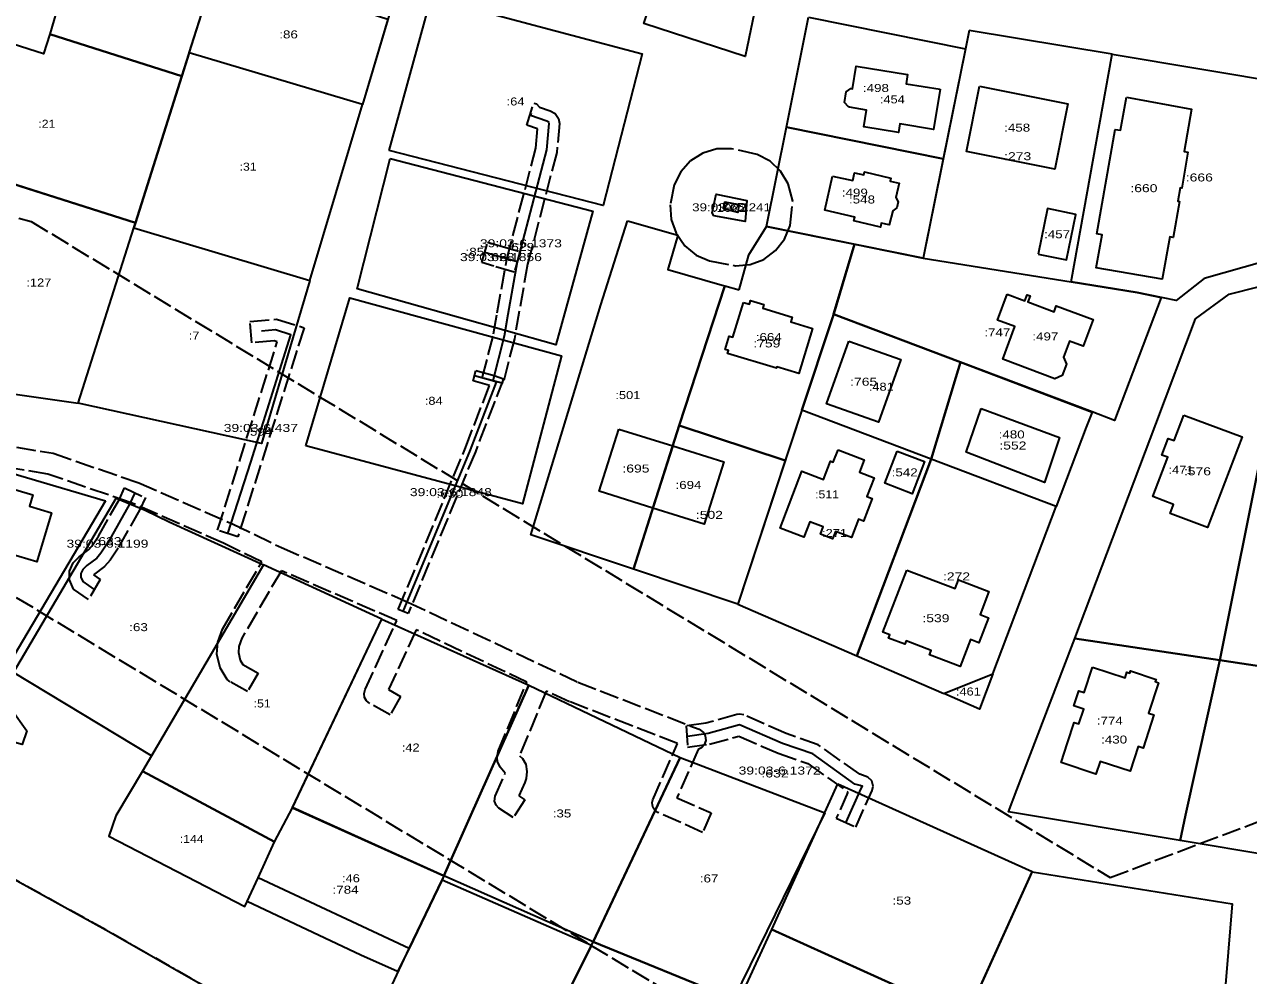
# Model space of a CAD drawing. Extents: x 1185507 to 1197690, y 352608 to 375774.
# Drawn here: x 1190677.6 to 1190907.1, y 364315.6 to 364493.9 of the extents above; entities that cross this region are included whole.
import ezdxf
from ezdxf.enums import TextEntityAlignment as Align

# ---------------------------------------------------------------- set-up
doc = ezdxf.new("R2010")
doc.units = 0
doc.header["$LTSCALE"] = 0.6
doc.linetypes.add('DOT_DASHED', pattern=[7.7, 5, -1.2, 0.3, -1.2])
doc.linetypes.add('LONG_DASHED', pattern=[7.5, 6, -1.5])
for name, color, linetype, lineweight in [('2', 7, 'Continuous', 35), ('4', 7, 'Continuous', 35), ('5', 7, 'DOT_DASHED', 35), ('7', 7, 'LONG_DASHED', 35), ('8', 7, 'Continuous', 35)]:
    doc.layers.add(name, color=color, linetype=linetype, lineweight=lineweight)

msp = doc.modelspace()

# ---------------------------------------------------------------- linework, layer by layer
at = {"layer": '2'}
for points in [[(1190719.02, 364521.51), (1190687.19, 364531.61), (1190680.16, 364509.45), (1190686.26, 364505.38), (1190682.39, 364492.06), (1190707.18, 364484.19)], [(1190719.02, 364521.51), (1190750.74, 364511.45), (1190741, 364478.87), (1190708.55, 364488.55)], [(1190713.83, 364505.16), (1190745.78, 364494.86), (1190741, 364478.87), (1190708.55, 364488.55)], [(1190794.51, 364502.32), (1190815.14, 364499.34), (1190812.76, 364487.9), (1190793.8, 364494.04), (1190796.36, 364501.72)], [(1190746, 364470.23), (1190753.87, 364498.94), (1190793.44, 364488.37), (1190786.14, 364459.95)], [(1190824.65, 364495.22), (1190854.06, 364489.3), (1190849.91, 364468.72), (1190820.51, 364474.64)], [(1190682.39, 364492.06), (1190681.23, 364488.39), (1190664.07, 364493.84), (1190656.51, 364470), (1190698.44, 364456.69), (1190707.18, 364484.19)], [(1190854.77, 364492.73), (1190854.06, 364489.3), (1190846.16, 364450.09), (1190873.92, 364445.64), (1190881.57, 364488.28)], [(1190708.55, 364488.55), (1190707.18, 364484.19), (1190698.44, 364456.69), (1190698.15, 364455.75), (1190731.18, 364445.9), (1190741, 364478.87)], [(1190881.57, 364488.28), (1190914.8, 364482.77), (1190921.92, 364481.47), (1190915.94, 364453.04), (1190913.8, 364450.48), (1190898.8, 364446.24), (1190893.57, 364442.12), (1190886.29, 364443.64), (1190873.92, 364445.64)], [(1190820.51, 364474.64), (1190849.91, 364468.72), (1190846.16, 364450.09), (1190816.75, 364456.02)], [(1190698.44, 364456.69), (1190662.46, 364468.12), (1190662.24, 364426.49), (1190687.72, 364422.9), (1190698.15, 364455.75)], [(1190746.24, 364468.74), (1190784.19, 364458.88), (1190777.27, 364433.8), (1190740, 364444.35)], [(1190806.88, 364458.01), (1190806.59, 364458.54), (1190807.34, 364462.04), (1190813.08, 364460.87), (1190812.79, 364456.95)], [(1190790.71, 364457.07), (1190800.12, 364454.38), (1190798.27, 364447.95), (1190808.46, 364445.03), (1190808.95, 364444.89), (1190800.4, 364418.7), (1190791.84, 364391.75), (1190772.61, 364398.19), (1190785.72, 364441.31)], [(1190698.15, 364455.75), (1190731.18, 364445.9), (1190722.07, 364415.36), (1190687.72, 364422.9)], [(1190811.63, 364444.12), (1190813.48, 364450.72), (1190816.75, 364456.02), (1190833.27, 364452.69), (1190829.37, 364439.63), (1190829.21, 364439.1), (1190823.42, 364421.57), (1190820.3, 364412.16), (1190800.4, 364418.7), (1190808.95, 364444.89)], [(1190833.27, 364452.69), (1190846.16, 364450.09), (1190873.92, 364445.64), (1190886.29, 364443.64), (1190890.75, 364442.71), (1190882.01, 364419.64), (1190877.8, 364421.24), (1190853.16, 364430.57), (1190829.36, 364439.59)], [(1190914.39, 364446.09), (1190909.87, 364415.25), (1190901.75, 364374.72), (1190874.57, 364378.76), (1190889.75, 364418.95), (1190897.19, 364438.67), (1190903.51, 364443.35)], [(1190914.39, 364446.09), (1190917.9, 364438.19), (1190925.84, 364435.48), (1190928.4, 364432.38), (1190929.16, 364411.7), (1190930.24, 364382.97), (1190930.46, 364376.9), (1190930.71, 364370.41), (1190917.36, 364372.4), (1190911.27, 364373.3), (1190901.75, 364374.72), (1190909.87, 364415.25)], [(1190730.4, 364414.92), (1190738.68, 364442.62), (1190778.35, 364431.75), (1190771.01, 364404.05)], [(1190829.21, 364439.1), (1190829.36, 364439.59), (1190853.16, 364430.57), (1190852.29, 364427.69), (1190847.67, 364412.37), (1190823.42, 364421.57)], [(1190852.29, 364427.69), (1190853.16, 364430.57), (1190877.8, 364421.23), (1190876.73, 364418.41), (1190871.08, 364403.5), (1190847.67, 364412.37)], [(1190823.42, 364421.57), (1190811.39, 364385.21), (1190833.72, 364375.54), (1190847.67, 364412.37)], [(1190800.4, 364418.7), (1190820.3, 364412.16), (1190811.39, 364385.21), (1190791.84, 364391.75)], [(1190692.85, 364404.6), (1190672.17, 364369.74), (1190678.11, 364361.49), (1190677.19, 364358.9), (1190651.89, 364365.81), (1190654.11, 364375.27), (1190663.17, 364413.36)], [(1190847.67, 364412.37), (1190833.72, 364375.54), (1190850.03, 364368.47), (1190859.2, 364372.14), (1190871.08, 364403.5)], [(1190694.85, 364405.06), (1190700.3, 364402.84), (1190704.79, 364400.65), (1190722.45, 364392.56), (1190701.47, 364356.76), (1190675.62, 364372.41)], [(1190722.45, 364392.56), (1190699.8, 364353.89), (1190724.53, 364340.65), (1190727.9, 364347.03), (1190744.63, 364382.42)], [(1190744.63, 364382.42), (1190772.2, 364370.06), (1190761.1, 364345.11), (1190756.27, 364334.27), (1190727.93, 364347.09)], [(1190874.57, 364378.76), (1190901.75, 364374.72), (1190895.36, 364345.65), (1190894.32, 364340.92), (1190862.14, 364346.31), (1190863.68, 364350.39), (1190873.96, 364377.16)], [(1190901.75, 364374.72), (1190911.27, 364373.3), (1190917.36, 364372.4), (1190930.71, 364370.41), (1190931.6, 364338.75), (1190914.65, 364338.2), (1190911.54, 364338.02), (1190894.32, 364340.92), (1190895.36, 364345.65)], [(1190850.03, 364368.47), (1190859.2, 364372.14), (1190856.72, 364365.55)], [(1190772.18, 364370.04), (1190800.59, 364356.46), (1190784.3, 364321.94), (1190756.27, 364334.27), (1190761.1, 364345.11)], [(1190800.59, 364356.46), (1190827.72, 364346.08), (1190810.56, 364311.15), (1190784.3, 364321.94)], [(1190724.53, 364340.65), (1190699.8, 364353.89), (1190694.75, 364345.53), (1190693.48, 364341.71), (1190718.98, 364328.52), (1190721.45, 364333.92)], [(1190830.12, 364351.57), (1190866.56, 364335.08), (1190854.19, 364307.74), (1190817.75, 364324.23)], [(1190727.9, 364347.03), (1190756.27, 364334.27), (1190755.93, 364333.55), (1190749.79, 364320.65), (1190747.6, 364316.36), (1190740.71, 364319.42), (1190719.43, 364329.5), (1190721.45, 364333.92), (1190724.53, 364340.65)], [(1190727.9, 364347.03), (1190756.27, 364334.27), (1190749.79, 364320.65), (1190721.45, 364333.92), (1190724.53, 364340.65)], [(1190866.56, 364335.07), (1190904.08, 364329.02), (1190899.68, 364276.2), (1190843.91, 364285.02), (1190854.19, 364307.74)], [(1190755.93, 364333.55), (1190783.97, 364321.28), (1190779.44, 364312.21), (1190772.48, 364297.77), (1190767.95, 364289.05), (1190741.88, 364303.85), (1190749.79, 364320.65)], [(1190841.33, 364280.15), (1190834.58, 364277.69), (1190809.79, 364289.26), (1190803.07, 364292.4), (1190811.54, 364310.75), (1190813.01, 364313.94), (1190817.75, 364324.23), (1190854.19, 364307.74), (1190843.91, 364285.02)], [(1190784.3, 364321.94), (1190810.56, 364311.15), (1190811.54, 364310.75), (1190803.07, 364292.4), (1190772.48, 364297.77), (1190779.44, 364312.21)]]:
    msp.add_lwpolyline(points, close=True, dxfattribs=at)
at = {"layer": '4'}
msp.add_lwpolyline([(1190647.14, 364349.43), (1190692.88, 364324.17), (1190757.05, 364287.63), (1190847.4, 364236.46), (1190870.47, 364225.86), (1190887.93, 364229.43), (1190903.2, 364233), (1190963.17, 364257.43), (1190977.58, 364249.06), (1191018.45, 364240.46), (1191053.56, 364275.17), (1191077.75, 364294.16)], dxfattribs=at)
at = {"layer": '5'}
msp.add_lwpolyline([(1190977.58, 364249.06), (1190963.17, 364257.43), (1190903.2, 364233), (1190887.93, 364229.43), (1190870.47, 364225.86), (1190847.4, 364236.46), (1190757.05, 364287.63), (1190692.88, 364324.17), (1190647.14, 364349.43), (1190632.21, 364356.82), (1190626.4, 364363.08), (1190622.19, 364369.01), (1190611.28, 364369.51), (1190595.22, 364367.23), (1190532.29, 364357.36), (1190463.09, 364355.18), (1190404.66, 364360.8), (1190352.99, 364368.35)], dxfattribs=at)
at = {"layer": '7'}
for points in [[(1189191.9, 364549.27), (1189395.22, 364588.56), (1189548.85, 364595.13), (1189680.04, 364579.91), (1189784.57, 364598.37), (1189872.95, 364591.01), (1190232.66, 364472.66), (1190283.77, 364463.98), (1190368.24, 364469.75), (1190452.8, 364459.37), (1190615.51, 364473.08), (1190678.91, 364456.96), (1190881.18, 364333.99), (1190940.56, 364356.34), (1190991.35, 364354.82), (1191177.32, 364502.05)], [(1189181.53, 364482.48), (1189344.66, 364521.04), (1189504.15, 364533.94), (1189608.74, 364531.21), (1189675.93, 364518.82), (1189812.58, 364539.7), (1189922.37, 364516.11), (1190113.06, 364450.97), (1190189.38, 364420.33), (1190281.14, 364404.98), (1190362.32, 364410.03), (1190480.68, 364396.9), (1190633.76, 364412.12), (1190877.81, 364264.44), (1190958.03, 364298.57), (1191010.79, 364286.96), (1191124.41, 364386.71)], [(1190671.72, 364415.36), (1190683.02, 364413.49), (1190699.1, 364407.95), (1190716.63, 364400.27), (1190725.81, 364395.84), (1190749.53, 364385.62), (1190781.42, 364370.6), (1190804.13, 364361.76), (1190804.93, 364361.18), (1190805.29, 364360.52), (1190805.37, 364359.65), (1190805.08, 364358.83), (1190804.57, 364358.28), (1190803.96, 364357.99), (1190799.99, 364348.93), (1190806.42, 364346.1), (1190804.8, 364342.44), (1190796.39, 364346.16), (1190795.88, 364346.56), (1190795.54, 364347.06), (1190795.38, 364347.53), (1190795.35, 364348.04), (1190795.45, 364348.53), (1190800.07, 364359.08), (1190779.86, 364366.92)], [(1190779.86, 364366.92), (1190775.48, 364368.92), (1190770.45, 364356.81), (1190771.01, 364356.28), (1190771.63, 364355.24), (1190771.86, 364353.84), (1190771.7, 364352.54), (1190771.46, 364351.76), (1190770.32, 364349.31), (1190771.46, 364348.57), (1190769.3, 364345.2), (1190766.59, 364346.96), (1190766.08, 364347.51), (1190765.8, 364348.26), (1190765.87, 364349.2), (1190767.8, 364353.56), (1190766.86, 364354.69), (1190766.36, 364355.75), (1190766.26, 364356.5), (1190766.46, 364357.64), (1190771.84, 364370.59), (1190751.09, 364380.43), (1190745.92, 364369.21), (1190748.16, 364367.94), (1190746.2, 364364.46), (1190742.37, 364366.62), (1190741.79, 364367.09), (1190741.43, 364367.75), (1190741.33, 364368.5), (1190741.52, 364369.22), (1190747.48, 364382.15), (1190725.81, 364391.49), (1190718.39, 364378.84), (1190717.85, 364377.28), (1190717.76, 364376.13), (1190718.08, 364374.71), (1190718.59, 364373.91), (1190721.46, 364372.27), (1190719.44, 364368.82), (1190716.21, 364370.65), (1190715.63, 364371.12), (1190714.31, 364373.31), (1190713.74, 364375.85), (1190713.91, 364378.07), (1190714.75, 364380.53), (1190722.16, 364393.16), (1190714.94, 364396.64), (1190697.63, 364404.23), (1190682.03, 364409.6), (1190671.12, 364411.4)]]:
    msp.add_lwpolyline(points, dxfattribs=at)
for points in [[(1190773.12, 364479.12), (1190773.62, 364478.99), (1190774.21, 364478.4), (1190776.2, 364477.72), (1190777.13, 364477.21), (1190777.78, 364476.23), (1190777.96, 364475.33), (1190777.44, 364469.87), (1190771.98, 364448.97), (1190769.5, 364434.98), (1190767.37, 364426.6), (1190763.49, 364427.59), (1190765.61, 364435.89), (1190766.29, 364439.84), (1190768.09, 364449.9), (1190773.53, 364470.72), (1190773.85, 364474.3), (1190771.86, 364474.98)], [(1190810.21, 364470.57), (1190807.48, 364470.54), (1190804.85, 364469.76), (1190802.54, 364468.31), (1190800.7, 364466.28), (1190799.48, 364463.83), (1190798.74, 364460.06), (1190798.91, 364457.33), (1190799.81, 364454.74), (1190801.45, 364452.4), (1190803.57, 364450.66), (1190806.08, 364449.57), (1190810.98, 364448.65), (1190813.71, 364448.88), (1190816.27, 364449.85), (1190818.47, 364451.48), (1190820.15, 364453.64), (1190821.18, 364456.17), (1190821.69, 364460.77), (1190820.81, 364464), (1190819.42, 364466.35), (1190817.43, 364468.24), (1190815.01, 364469.52)], [(1190770.58, 364451.31), (1190769.48, 364447.47), (1190765.67, 364448.56), (1190763.38, 364449.23), (1190764.48, 364453.07), (1190766.81, 364452.4)], [(1190719.92, 364438.2), (1190724.92, 364438.64), (1190730.07, 364437.03), (1190717.66, 364397.86), (1190713.86, 364399.08), (1190725.05, 364434.41), (1190724.48, 364434.58), (1190720.26, 364434.22)], [(1190749.57, 364383.44), (1190747.73, 364384.2), (1190760.32, 364414.52), (1190764.83, 364426.22), (1190761.76, 364427.07), (1190762.3, 364428.99), (1190765.68, 364428.05), (1190767.45, 364427.46), (1190762.18, 364413.78)], [(1190696.41, 364407), (1190700.32, 364405.19), (1190699.26, 364402.95), (1190695.21, 364395.74), (1190693.69, 364393.44), (1190692.64, 364392.26), (1190690.57, 364390.69), (1190691.83, 364389.83), (1190689.66, 364386.11), (1190686.86, 364388.03), (1190686.09, 364389.8), (1190686.09, 364391.42), (1190686.79, 364392.96), (1190687.88, 364394.11), (1190689.74, 364395.46), (1190690.27, 364396.06), (1190691.53, 364397.98), (1190695.44, 364404.91)], [(1190836.49, 364352.09), (1190835.76, 364352.82), (1190834.24, 364353.32), (1190826.46, 364358.88), (1190820.47, 364360.96), (1190812.53, 364364.45), (1190811.73, 364364.62), (1190811.18, 364364.54), (1190805.42, 364362.91), (1190801.7, 364362.41), (1190801.97, 364358.43), (1190806.09, 364358.96), (1190811.58, 364360.5), (1190818.94, 364357.27), (1190824.53, 364355.35), (1190832.05, 364349.97), (1190829.84, 364345.1), (1190833.5, 364343.44), (1190836.58, 364350.26), (1190836.76, 364351.09)]]:
    msp.add_lwpolyline(points, close=True, dxfattribs=at)
at = {"layer": '8'}
for points in [[(1190849.31, 364481.73), (1190848.1, 364474.21), (1190841.75, 364475.23), (1190841.49, 364473.6), (1190835.01, 364474.67), (1190835.53, 364477.84), (1190832.36, 364478.38), (1190832.13, 364478.41), (1190831.41, 364479.28), (1190831.72, 364481.26), (1190832.58, 364481.87), (1190832.87, 364481.84), (1190833.57, 364486.08), (1190843.22, 364484.48), (1190842.96, 364482.75)], [(1190856.73, 364482.33), (1190873.26, 364479), (1190870.8, 364466.74), (1190854.28, 364470.07)], [(1190884.24, 364480.25), (1190896.48, 364478), (1190895.11, 364470.09), (1190895.78, 364469.96), (1190894.62, 364463.19), (1190894.35, 364463.24), (1190893.89, 364460.76), (1190894.18, 364460.7), (1190893.02, 364453.93), (1190892.39, 364454.05), (1190890.93, 364446.13), (1190878.58, 364448.29), (1190879.71, 364454.47), (1190878.69, 364454.65), (1190882.15, 364474.2), (1190883.13, 364474.04)], [(1190829.17, 364465.45), (1190832.95, 364464.61), (1190833.3, 364466.08), (1190835.02, 364465.68), (1190835.15, 364466.23), (1190840.07, 364465.06), (1190839.94, 364464.53), (1190841.66, 364464.13), (1190841.04, 364461.46), (1190841.44, 364460.62), (1190841.19, 364459.51), (1190840.44, 364458.95), (1190839.8, 364456.29), (1190838.3, 364456.63), (1190838.13, 364455.91), (1190833.16, 364457.07), (1190833.32, 364457.76), (1190827.69, 364459.05)], [(1190808.72, 364459.31), (1190808.97, 364460.64), (1190811.59, 364460.11), (1190811.41, 364458.65)], [(1190867.71, 364450.84), (1190873, 364449.75), (1190874.79, 364458.24), (1190869.44, 364459.36)], [(1190861.92, 364443.33), (1190865.23, 364442.09), (1190865.65, 364443.19), (1190866.18, 364442.99), (1190865.76, 364441.87), (1190870.69, 364440.03), (1190871.1, 364441.13), (1190878, 364438.55), (1190876.14, 364433.57), (1190873.61, 364434.51), (1190872.44, 364431.5), (1190873.02, 364430.22), (1190872.21, 364428.07), (1190870.86, 364427.47), (1190861.07, 364431.14), (1190863.36, 364437.25), (1190860.1, 364438.47)], [(1190812.45, 364441.78), (1190813.6, 364441.47), (1190813.79, 364442.11), (1190816.3, 364441.36), (1190816.1, 364440.69), (1190821.58, 364439.04), (1190821.31, 364438.15), (1190825.4, 364436.88), (1190822.82, 364428.46), (1190818.71, 364429.73), (1190818.62, 364429.45), (1190809.48, 364432.18), (1190809.66, 364432.76), (1190808.99, 364432.96), (1190809.76, 364435.46), (1190810.43, 364435.26)], [(1190832.21, 364434.52), (1190841.95, 364431.05), (1190837.77, 364419.31), (1190828.03, 364422.78)], [(1190857.01, 364421.88), (1190871.73, 364416.44), (1190868.92, 364408.03), (1190854.21, 364413.73)], [(1190895.02, 364420.66), (1190905.94, 364416.56), (1190899.47, 364399.58), (1190892.47, 364402.21), (1190893.1, 364403.88), (1190889.2, 364405.38), (1190892.02, 364412.76), (1190890.88, 364413.14), (1190892.06, 364416.3), (1190893.2, 364415.92)], [(1190789.1, 364418.05), (1190799.19, 364414.9), (1190795.48, 364403.23), (1190785.4, 364406.37)], [(1190799.2, 364414.9), (1190808.8, 364411.91), (1190805.1, 364400.23), (1190795.49, 364403.23)], [(1190830.18, 364414.14), (1190835.11, 364412.26), (1190834.23, 364409.95), (1190836.94, 364408.92), (1190835.6, 364405.37), (1190836.58, 364405), (1190834.97, 364400.77), (1190833.99, 364401.14), (1190832.68, 364397.71), (1190829.7, 364398.84), (1190829.17, 364397.46), (1190826.87, 364398.33), (1190827.4, 364399.72), (1190824.89, 364400.67), (1190823.78, 364397.77), (1190819.31, 364399.46), (1190823.37, 364410.15), (1190827.44, 364408.6), (1190828.75, 364412.03), (1190829.3, 364411.82)], [(1190841.26, 364413.92), (1190846.39, 364411.97), (1190844.1, 364405.92), (1190838.96, 364407.87)], [(1190663.04, 364398.15), (1190665.74, 364407.29), (1190669.82, 364406.08), (1190670.47, 364408.26), (1190679.19, 364405.68), (1190678.57, 364403.56), (1190682.71, 364402.34), (1190679.99, 364393.14)], [(1190843.06, 364391.62), (1190852.14, 364388.14), (1190852.75, 364389.75), (1190858.47, 364387.58), (1190856.83, 364383.29), (1190858.41, 364382.67), (1190856.61, 364377.98), (1190855.03, 364378.59), (1190853.09, 364373.55), (1190847.35, 364375.73), (1190847.66, 364376.54), (1190842.94, 364378.34), (1190842.69, 364377.69), (1190839.67, 364378.84), (1190839.92, 364379.49), (1190838.61, 364379.99)], [(1190877.87, 364373.43), (1190884.02, 364371.43), (1190884.36, 364372.45), (1190884.9, 364372.27), (1190885.04, 364372.69), (1190889.8, 364371.12), (1190889.66, 364370.7), (1190890.28, 364370.5), (1190888.41, 364364.8), (1190889.37, 364364.5), (1190887.4, 364358.23), (1190886.44, 364358.53), (1190884.94, 364353.89), (1190879.31, 364355.71), (1190878.54, 364353.34), (1190872, 364355.54), (1190873.22, 364359.23), (1190874.48, 364363.05), (1190875.35, 364362.76), (1190876.26, 364365.53), (1190874.37, 364366.16), (1190875.32, 364368.97), (1190876.33, 364368.64)]]:
    msp.add_lwpolyline(points, close=True, dxfattribs=at)
for points in [[(1190772.62, 364477.26), (1190772.51, 364476.87), (1190775.56, 364475.83), (1190775.74, 364475.76), (1190775.86, 364475.67), (1190775.89, 364475.57), (1190775.96, 364475.33), (1190775.51, 364470.38), (1190770.03, 364449.39), (1190768.26, 364439.5), (1190767.56, 364435.47), (1190765.43, 364427.09)], [(1190770.03, 364449.39), (1190766.24, 364450.48), (1190765.85, 364450.6), (1190763.93, 364451.15)], [(1190715.76, 364398.47), (1190720.06, 364411.83), (1190727.56, 364435.72), (1190724.7, 364436.61), (1190722.08, 364436.38)], [(1190748.65, 364383.82), (1190761.25, 364414.15), (1190766.14, 364426.84), (1190765.39, 364427.09), (1190762.03, 364428.03)], [(1190698.36, 364406.09), (1190697.35, 364403.93), (1190693.37, 364396.86), (1190691.98, 364394.75), (1190691.19, 364393.86), (1190689.31, 364392.49), (1190688.6, 364391.74), (1190688.24, 364390.95), (1190688.24, 364390.25), (1190688.59, 364389.45), (1190690.73, 364387.97)], [(1190831.68, 364344.34), (1190834.55, 364350.64), (1190834.76, 364351.09), (1190834.61, 364351.13), (1190834.32, 364351.22), (1190833.36, 364351.49), (1190825.46, 364357.15), (1190819.74, 364359.1), (1190811.73, 364362.62), (1190805.83, 364360.95), (1190801.97, 364360.43)]]:
    msp.add_lwpolyline(points, dxfattribs=at)

# ---------------------------------------------------------------- texts
at = {"layer": '2'}
for s, width, p in [(':86', 1.25, (1190727.1645, 364491.265)), (':498', 1.25, (1190837.2855, 364481.22)), (':64', 1.2, (1190769.7195, 364478.695)), (':21', 1.15, (1190681.845, 364474.515)), (':273', 1.3, (1190863.8655, 364468.435)), (':31', 1.15, (1190719.575, 364466.475)), (':666', 1.3, (1190897.9205, 364464.45)), (':499', 1.25, (1190833.3305, 364461.615)), (':1022', 1.25, (1190809.835, 364458.745)), (':85', 1.25, (1190762.0945, 364450.52)), (':127', 1.2, (1190680.34, 364444.76)), (':7', 1.2, (1190709.4505, 364434.805)), (':747', 1.25, (1190860.0555, 364435.415)), (':759', 1.3, (1190816.8355, 364433.34)), (':481', 1.2, (1190838.29, 364425.23)), (':84', 1.2, (1190754.3745, 364422.585)), (':501', 1.2, (1190790.78, 364423.66)), (':480', 1.25, (1190862.7355, 364416.285)), (':471', 1.2, (1190894.48, 364409.655)), (':502', 1.3, (1190806.0705, 364401.205)), (':271', 1.2, (1190829.53, 364397.805)), (':272', 1.3, (1190852.4005, 364389.67)), (':63', 1.25, (1190699.0345, 364380.16)), (':461', 1.2, (1190854.615, 364368.095)), (':51', 1.15, (1190722.215, 364365.855)), (':430', 1.25, (1190881.9455, 364359.09)), (':42', 1.2, (1190750.0645, 364357.595)), (':35', 1.25, (1190778.4295, 364345.24)), (':144', 1.15, (1190709.0045, 364340.455)), (':46', 1.2, (1190738.8595, 364333.09)), (':67', 1.25, (1190806.0095, 364333.055)), (':784', 1.25, (1190737.8505, 364330.945)), (':53', 1.25, (1190842.1545, 364328.905))]:
    msp.add_text(s, height=1.5, dxfattribs=dict(at, width=width)).set_placement(p, align=Align.CENTER)
at = {"layer": '7'}
for s, width, p in [('39:03-6.1241', 1.25, (1190810.2145, 364458.86)), ('39:03-6.1373', 1.3, (1190770.7255, 364452.11)), ('39:03-6.1856', 1.3, (1190766.9805, 364449.52)), ('39:03-6.437', 1.3, (1190721.9645, 364417.5)), ('39:03-6.1848', 1.3, (1190757.59, 364405.465)), ('39:03-6.1199', 1.3, (1190693.205, 364395.805)), ('39:03-6.1372', 1.3, (1190819.2305, 364353.28))]:
    msp.add_text(s, height=1.5, dxfattribs=dict(at, width=width)).set_placement(p, align=Align.CENTER)
at = {"layer": '8'}
for s, width, p in [(':454', 1.2, (1190840.36, 364479.09)), (':458', 1.25, (1190863.7705, 364473.785)), (':660', 1.3, (1190887.5305, 364462.44)), (':548', 1.25, (1190834.6755, 364460.32)), (':775', 1.3, (1190810.1555, 364458.895)), (':457', 1.25, (1190871.2505, 364453.805)), (':629', 1.3, (1190770.6955, 364451.425)), (':628', 1.3, (1190766.9805, 364449.52)), (':664', 1.25, (1190817.1955, 364434.535)), (':497', 1.25, (1190869.0505, 364434.65)), (':765', 1.3, (1190834.9905, 364426.165)), (':594', 1.25, (1190721.6605, 364416.79)), (':552', 1.3, (1190862.9705, 364414.205)), (':695', 1.3, (1190792.2955, 364409.89)), (':542', 1.25, (1190842.6755, 364409.17)), (':576', 1.3, (1190897.5705, 364409.37)), (':694', 1.25, (1190802.1455, 364406.815)), (':630', 1.3, (1190757.3955, 364405.175)), (':511', 1.15, (1190828.1245, 364405.05)), (':633', 1.3, (1190693.3005, 364396.28)), (':539', 1.3, (1190848.5405, 364381.835)), (':774', 1.25, (1190881.1405, 364362.635)), (':632', 1.3, (1190818.3655, 364352.73))]:
    msp.add_text(s, height=1.5, dxfattribs=dict(at, width=width)).set_placement(p, align=Align.CENTER)

doc.saveas('drawing.dxf')
